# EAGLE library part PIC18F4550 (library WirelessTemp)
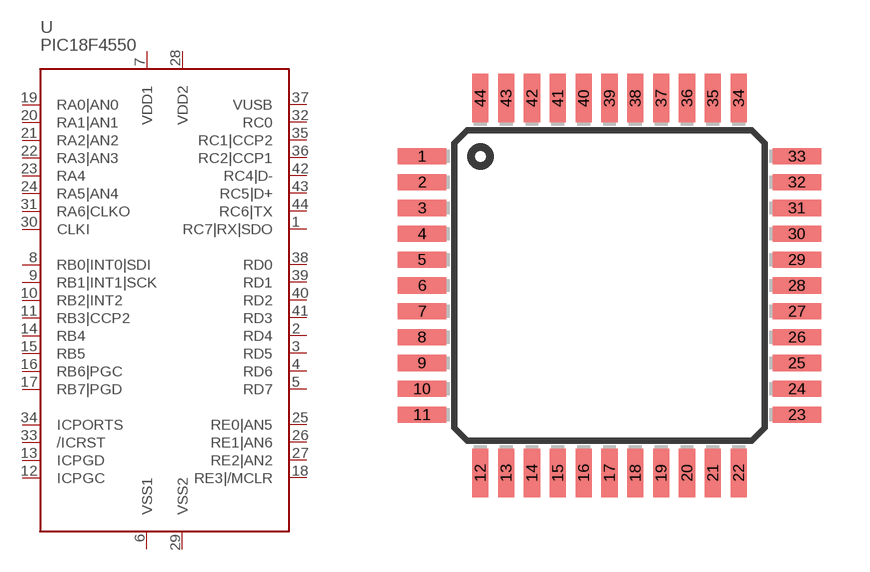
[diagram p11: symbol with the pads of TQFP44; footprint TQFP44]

Designator prefix -

## PIC18F4550  [TQFP44]
1  RC7|RX|SDO
2  RD4
3  RD5
4  RD6
5  RD7
6  VSS1  pwr
7  VDD1  pwr
8  RB0|INT0|SDI
9  RB1|INT1|SCK
10  RB2|INT2
11  RB3|CCP2
12  ICPGC
13  ICPGD
14  RB4
15  RB5
16  RB6|PGC
17  RB7|PGD
18  RE3|/MCLR  in
19  RA0|AN0
20  RA1|AN1
21  RA2|AN2
22  RA3|AN3
23  RA4
24  RA5|AN4
25  RE0|AN5
26  RE1|AN6
27  RE2|AN2
28  VDD2  pwr
29  VSS2  pwr
30  CLKI  in
31  RA6|CLKO
32  RC0
33  /ICRST  in
34  ICPORTS  in
35  RC1|CCP2
36  RC2|CCP1
37  VUSB  pwr
38  RD0
39  RD1
40  RD2
41  RD3
42  RC4|D-
43  RC5|D+
44  RC6|TX

## Footprint TQFP44 (pad centres in mm)
Thin Quad Flat Pack package type TQ
smd 1.5 x 0.5: 1 -5.8,4; 2 -5.8,3.2; 3 -5.8,2.4; 4 -5.8,1.6; 5 -5.8,0.8; 6 -5.8,0; 7 -5.8,-0.8; 8 -5.8,-1.6; 9 -5.8,-2.4; 10 -5.8,-3.2; 11 -5.8,-4; 23 5.8,-4; 24 5.8,-3.2; 25 5.8,-2.4; 26 5.8,-1.6; 27 5.8,-0.8; 28 5.8,0; 29 5.8,0.8; 30 5.8,1.6; 31 5.8,2.4; 32 5.8,3.2; 33 5.8,4
smd 0.5 x 1.5: 12 -4,-5.8; 13 -3.2,-5.8; 14 -2.4,-5.8; 15 -1.6,-5.8; 16 -0.8,-5.8; 17 0,-5.8; 18 0.8,-5.8; 19 1.6,-5.8; 20 2.4,-5.8; 21 3.2,-5.8; 22 4,-5.8; 34 4,5.8; 35 3.2,5.8; 36 2.4,5.8; 37 1.6,5.8; 38 0.8,5.8; 39 0,5.8; 40 -0.8,5.8; 41 -1.6,5.8; 42 -2.4,5.8; 43 -3.2,5.8; 44 -4,5.8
